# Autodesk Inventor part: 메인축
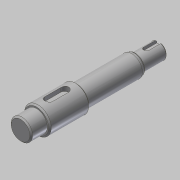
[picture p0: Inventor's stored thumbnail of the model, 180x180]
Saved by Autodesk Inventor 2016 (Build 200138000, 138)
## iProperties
Created: 2019-03
Part Number: 메인축
Material: 강철, 연강
Document SubType Name: Modeling
Designer: mduedu
Density: 1 g/cm^3
Appearance: 강철
Author: mduedu
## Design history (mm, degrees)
sketch "스케치1"
  geometry: L1 (0, 0)-(12, 0); L2 (12, 0)-(12, 8); L3 (12, 8)-(0, 8); L4 (0, 8)-(0, 0); L5 (12, 0)-(42, 0); L6 (42, 0)-(42, 10); L7 (42, 10)-(12, 10); L8 (12, 10)-(12, 0); L9 (42, 0)-(86, 0); L10 (86, 0)-(86, 8); L11 (86, 8)-(42, 8); L12 (42, 8)-(42, 0); L13 (86, 0)-(104, 0); L14 (104, 0)-(104, 6); L15 (104, 6)-(86, 6); L16 (86, 6)-(86, 0)
  constraints: 32 end point, 8 parallel, 4 horizontal, 4 perpendicular
  dimensions: "d0" = 16 diameter of L3 L1; "d2" = 20 diameter of L7 L5; "d3" = 16 diameter of L11 L9; "d4" = 12 diameter of L15 L13; "d5" = 12 distance of L2.end L3.end; "d6" = 30 distance of L6.end L7.end; "d7" = 86 distance between parallel lines of L10 L4; "d8" = 104 distance between parallel lines of L14 L4
revolve "회전1" sketch "스케치1" stored, may be unused: angle "d9" = 90 deg
node "작업 평면1"
sketch "스케치2" dims "d10" = 18
  geometry: L1 (6, -3)-(-6, -3); L2 (-6, -3)-(-6, 3); L3 (-6, 3)-(6, 3); L4 (6, 3)-(6, -3); L5 (15, 10)-(15, -10) reference; 3 further points
  constraints: 8 end point, 2 midpoint, 2 parallel, 2 vertical alignment, 1 horizontal, 1 horizontal alignment, 1 perpendicular, 4 other
  dimensions: "d12" = 6 distance between parallel lines of L3 L1; "d13" = 6 dimension on L5
extrude "돌출1" cut sketch "스케치2" distance "d14" = 3.5; taper "d15" = 0 deg
node "작업 평면2"
sketch "스케치3"
  geometry: L1 (-9, 6)-(-9, -6) reference; L2 (1, -2)-(-9, -2); L3 (1, 2)-(-9, 2); A1 r 2 centre (1, 0) between (1, -2) and (1, 2); 2 further points
  constraints: 4 end point, 2 point on circle, 2 point on line, 2 tangent, 1 centre point, 1 horizontal alignment, 1 midpoint, 1 parallel, 1 perpendicular
  dimensions: "d16" = 12 dimension on A1 L1; "d17" = 4 distance between parallel lines of L3 L2
extrude "돌출2" cut sketch "스케치3" distance "d18" = 2.5; taper "d19" = 0 deg
chamfer "모따기1" distance "d20" = 1; stored, may be unused: second distance "d21" = 2, angle "d22" = 45 deg
chamfer "모따기2" distance "d23" = 1; stored, may be unused: second distance "d24" = 2, angle "d25" = 45 deg
chamfer "모따기3" distance "d26" = 1.73; stored, may be unused: second distance "d27" = 2, angle "d28" = 30 deg
fillet "모깎기2" dims "d31" = 0.5, "d32" = 4
node "솔리드1"
